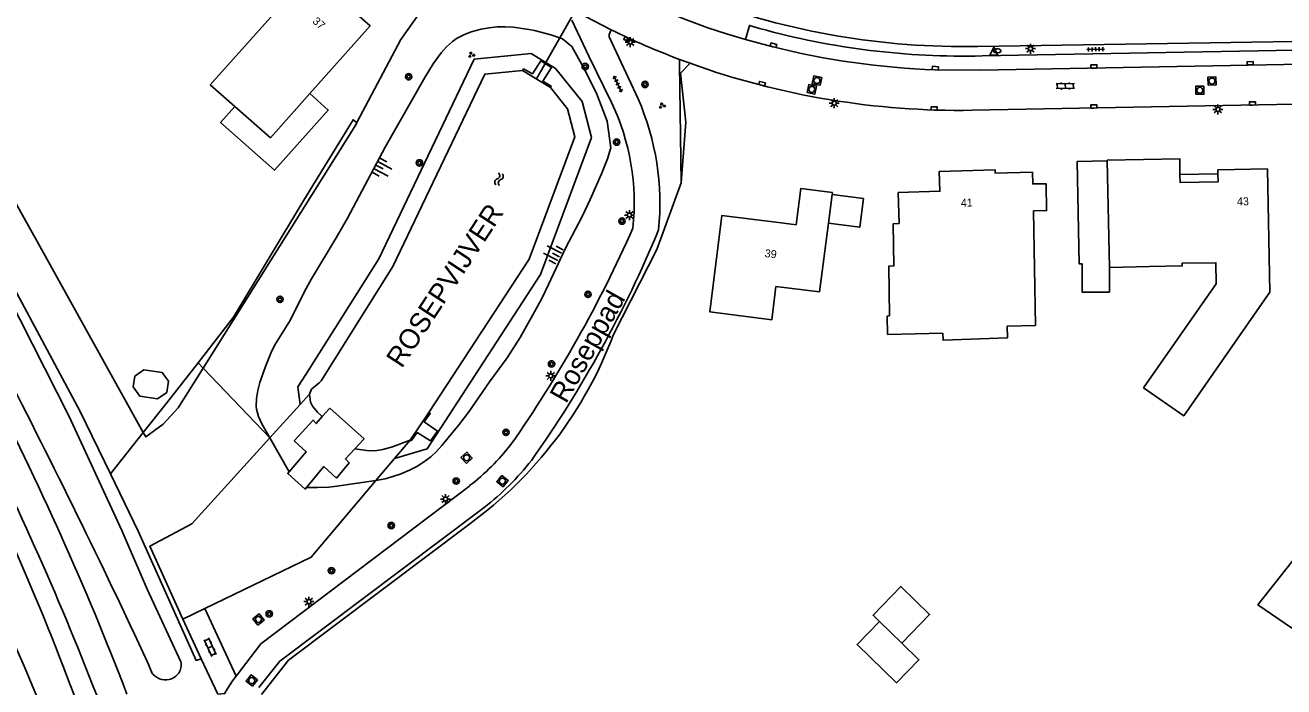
# Model space of a CAD drawing. Extents: x 126000 to 131009, y 393000 to 395500.
# Drawn here: x 130394.9 to 130552.1, y 394768.1 to 394850.8 of the extents above; entities that cross this region are included whole.
import ezdxf

# ---------------------------------------------------------------- set-up
doc = ezdxf.new("R2010")
doc.units = 0
for name, color, linetype in [('gg-afsc-erfafscheiding', 7, 'Continuous'), ('gg-afsc-hekwerk', 7, 'Continuous'), ('gg-anno-huisnummerreeks BGT', 7, 'Continuous'), ('gg-anno-naam water', 7, 'Continuous'), ('gg-anno-openbare ruimte label', 7, 'Continuous'), ('gg-bbg-gedigitaliseerde bebouwing', 7, 'Continuous'), ('gg-bbg-gedigitaliseerde bijgebouw', 7, 'Continuous'), ('gg-bbg-hoofdgebouw', 7, 'Continuous'), ('gg-bbg-luifel en loopbrug', 7, 'Continuous'), ('gg-knt-bovenkant onderkant talud', 7, 'Continuous'), ('gg-knt-verharding', 7, 'Continuous'), ('gg-knt-verharding nz', 7, 'Continuous'), ('gg-kntw-beschoeiing', 7, 'Continuous'), ('gg-kntw-bovenkant insteek waterloop', 7, 'Continuous'), ('gg-kwrk-duiker nz buis', 7, 'Continuous'), ('gg-kwrk-gemaal', 7, 'Continuous'), ('gg-kwrk-uitstroombak niveau min 01', 7, 'Continuous'), ('gt-grn-groengrens', 7, 'Continuous'), ('gt-symb-boom', 7, 'Continuous'), ('gt-symb-brandkraan', 7, 'Continuous'), ('gt-symb-groenvak', 7, 'Continuous'), ('gt-symb-klinker verharding', 7, 'Continuous'), ('gt-symb-kolk', 7, 'Continuous'), ('gt-symb-lichtmast', 7, 'Continuous'), ('gt-symb-rioolschacht', 7, 'Continuous'), ('gt-symb-talud symbool', 7, 'Continuous'), ('gt-symb-tegel verharding', 7, 'Continuous'), ('gt-symb-waterafsluiter', 7, 'Continuous'), ('gt-symb-watersymbool', 7, 'Continuous')]:
    doc.layers.add(name, color=color, linetype=linetype)

# ---------------------------------------------------------------- blocks, each defined once
blk = doc.blocks.new('gt0-RS')
at = {"layer": 'gt-symb-rioolschacht'}
blk.add_lwpolyline([(-0.5, -0.5), (0.5, -0.5), (0.5, 0.5), (-0.5, 0.5)], close=True, dxfattribs=at)
blk.add_circle((0, 0), 0.375, dxfattribs=at)
blk = doc.blocks.new('gt0-KOLK')
at = {"layer": 'gt-symb-kolk'}
blk.add_lwpolyline([(0, 0), (0.38, 0), (0.38, 0.4), (-0.37, 0.4), (-0.37, 0), (0, 0)], dxfattribs=at)
blk = doc.blocks.new('gt0-WAFSL')
at = {"layer": 'gt-symb-waterafsluiter'}
for p, q in [((-0.5, -0.33), (0, 0.67)), ((0, 0.67), (0.5, -0.33)), ((0.5, -0.33), (-0.5, -0.33))]:
    blk.add_line(p, q, dxfattribs=at)
blk = doc.blocks.new('gt0-BR')
at = {"layer": 'gt-symb-brandkraan'}
for centre, radius, start, end in [((-0.24, 0), 0.206, 107.5669, 252.4331), ((0.6, -2.66), 3, 106.892, 107.5669), ((0, -0.69), 0.938, 73.108, 106.892), ((-0.6, -2.66), 3, 72.4331, 73.108), ((0.24, 0), 0.206, 287.567, 72.4331), ((0.6, 2.66), 3, 252.4331, 253.108), ((0, 0.69), 0.938, 253.108, 286.8921), ((-0.6, 2.66), 3, 286.8921, 287.567)]:
    blk.add_arc(centre, radius, start, end, dxfattribs=at)
blk = doc.blocks.new('gt0-LMAST')
at = {"layer": 'gt-symb-lichtmast'}
for p, q in [((-0.18, 0.17), (-0.45, 0.44)), ((0, 0.25), (0, 0.62)), ((0.17, 0.17), (0.44, 0.44)), ((-0.25, 0), (-0.63, 0)), ((-0.18, -0.18), (-0.45, -0.45)), ((0, -0.25), (0, -0.63)), ((0.44, -0.45), (0.17, -0.18)), ((0.25, 0), (0.62, 0))]:
    blk.add_line(p, q, dxfattribs=at)
blk.add_circle((0, 0), 0.25, dxfattribs=at)
blk = doc.blocks.new('gt0-KL1')
at = {"layer": 'gt-symb-klinker verharding'}
for p, q in [((-1.15, 0.3), (1.15, 0.3)), ((-1, -0.3), (-1, 0.3)), ((-0.5, 0.3), (-0.5, 0.45)), ((0, -0.3), (0, 0.3)), ((0.5, 0.3), (0.5, 0.45)), ((1, -0.3), (1, 0.3)), ((-1.15, -0.3), (1.15, -0.3)), ((-0.5, -0.45), (-0.5, -0.3)), ((0.5, -0.45), (0.5, -0.3))]:
    blk.add_line(p, q, dxfattribs=at)
blk = doc.blocks.new('gt0-TEG1')
at = {"layer": 'gt-symb-tegel verharding'}
for p, q in [((-1.12, 0), (1.12, 0)), ((-0.9, -0.25), (-0.9, 0.25)), ((-0.45, -0.25), (-0.45, 0.25)), ((0, -0.25), (0, 0.25)), ((0.45, -0.25), (0.45, 0.25)), ((0.9, -0.25), (0.9, 0.25))]:
    blk.add_line(p, q, dxfattribs=at)
blk = doc.blocks.new('gt0-GRVAK')
at = {"layer": 'gt-symb-groenvak'}
for p, q in [((-0.11, 0.19), (-0.23, 0.24)), ((-0.18, 0.15), (0.09, 0.15)), ((-0.09, 0.21), (-0.16, 0.32)), ((-0.05, 0.21), (-0.05, 0.39)), ((0, 0.21), (0.06, 0.32)), ((0.01, 0.19), (0.13, 0.24)), ((0.26, -0.05), (0.2, 0.06)), ((0.3, -0.05), (0.3, 0.13)), ((0.35, -0.05), (0.41, 0.06)), ((-0.25, -0.23), (-0.36, -0.18)), ((-0.32, -0.26), (-0.05, -0.26)), ((-0.23, -0.21), (-0.29, -0.1)), ((-0.18, -0.2), (-0.18, -0.02)), ((-0.14, -0.21), (-0.07, -0.1)), ((-0.12, -0.23), (0, -0.18)), ((0.24, -0.07), (0.12, -0.02)), ((0.17, -0.11), (0.44, -0.11)), ((0.37, -0.07), (0.49, -0.02))]:
    blk.add_line(p, q, dxfattribs=at)
blk = doc.blocks.new('gt0-BOOM')
at = {"layer": 'gt-symb-boom'}
for radius in [0.4, 0.2]:
    blk.add_circle((0, 0), radius, dxfattribs=at)
blk = doc.blocks.new('gt0-TALUD_1')
at = {"layer": 'gt-symb-talud symbool'}
for p, q in [((-1, -1), (-1, 0)), ((-0.5, -2), (-0.5, 0)), ((0, -1), (0, 0)), ((0.5, -2), (0.5, 0)), ((1, -1), (1, 0))]:
    blk.add_line(p, q, dxfattribs=at)
blk = doc.blocks.new('gt0-WA')
at = {"layer": 'gt-symb-watersymbool'}
for centre, start, end in [((-0.32, 0.02), 28.0725, 151.9275), ((0.43, 0.42), 208.0725, 331.9275), ((-0.32, -0.43), 28.0725, 151.9275), ((0.43, -0.03), 208.0725, 331.9275)]:
    blk.add_arc(centre, 0.425, start, end, dxfattribs=at)

msp = doc.modelspace()

# ---------------------------------------------------------------- linework, layer by layer
at = {"layer": 'gg-afsc-erfafscheiding'}
for p, q in [((130476.62, 394845.94), (130476.81, 394831.13)), ((130476.81, 394831.13), (130473.77, 394822.79))]:
    msp.add_line(p, q, dxfattribs=at)
at = {"layer": 'gg-afsc-hekwerk'}
for p, q in [((130436.3, 394838.67), (130441.81, 394849.05)), ((130473.77, 394822.79), (130468.38, 394812.17)), ((130429.2, 394803.42), (130430.38, 394804.72)), ((130425.43, 394799.26), (130429.2, 394803.42)), ((130442.96, 394798.98), (130441.02, 394796.68)), ((130441.02, 394796.68), (130438.68, 394793.9)), ((130417.29, 394777.92), (130414.54, 394776.6))]:
    msp.add_line(p, q, dxfattribs=at)
for points in [[(130381.11, 394841.01), (130385.07, 394843.99), (130396.51, 394823.51), (130409.61, 394799.92)], [(130417.1, 394807.96), (130436.16, 394838.39), (130436.3, 394838.67)], [(130409.61, 394799.92), (130409.92, 394799.36), (130412.12, 394800.98), (130413.99, 394803), (130417.1, 394807.96)], [(130414.54, 394776.6), (130410.44, 394785.72), (130415.68, 394788.51), (130425.43, 394799.26)], [(130438.68, 394793.9), (130430.6, 394784.32), (130417.29, 394777.92)], [(130424.38, 394767.15), (130427.75, 394771.45), (130450.41, 394788.5)]]:
    msp.add_lwpolyline(points, dxfattribs=at)
msp.add_arc((130419.91, 394830.31), 51.75, 306.1088, 339.4837, dxfattribs=at)
at = {"layer": 'gg-bbg-gedigitaliseerde bebouwing'}
for p, q in [((130421.06, 394840.69), (130425.51, 394836.77)), ((130530.07, 394833.89), (130530.06, 394833.97)), ((130530.34, 394820.56), (130530.07, 394833.89)), ((130495.69, 394829.66), (130495.23, 394826.09)), ((130495.73, 394829.93), (130495.69, 394829.66)), ((130503.95, 394829.94), (130504.06, 394826.03)), ((130521.12, 394813.29), (130520.84, 394827.63)), ((130535.34, 394820.66), (130530.34, 394820.56))]:
    msp.add_line(p, q, dxfattribs=at)
for points in [[(130433.8, 394861.11), (130417.99, 394843.39), (130421.06, 394840.69)], [(130520.84, 394827.63), (130522.48, 394827.66), (130522.43, 394831.02), (130520.77, 394830.99), (130520.74, 394832.45)], [(130495.23, 394826.09), (130494.13, 394817.51), (130488.67, 394818.19)], [(130502.88, 394814.49), (130502.78, 394820.73), (130503.42, 394820.74), (130503.32, 394826.02), (130504.06, 394826.03)], [(130534.62, 394805.49), (130543.69, 394818.52), (130543.64, 394821.15), (130539.43, 394821.07), (130539.44, 394820.75), (130535.34, 394820.66)], [(130550.4, 394817.48), (130539.63, 394802), (130534.62, 394805.49)], [(130502.88, 394814.49), (130502.58, 394814.48), (130502.62, 394812.18), (130509.54, 394812.32)], [(130521.12, 394813.29), (130517.58, 394813.21), (130517.61, 394811.76), (130509.56, 394811.46), (130509.54, 394812.32)]]:
    msp.add_lwpolyline(points, dxfattribs=at)
at = {"layer": 'gg-bbg-gedigitaliseerde bijgebouw'}
msp.add_line((130501.61, 394776.3), (130504.39, 394773.6), dxfattribs=at)
for points in [[(130408.37, 394805.62), (130408.57, 394806.96), (130409.7, 394807.76), (130411.96, 394807.41), (130412.76, 394806.33), (130412.55, 394804.93), (130411.38, 394804.14), (130409.18, 394804.48), (130408.37, 394805.62)], [(130504.39, 394773.6), (130506.54, 394771.51), (130503.75, 394768.64), (130498.82, 394773.43), (130501.61, 394776.3)]]:
    msp.add_lwpolyline(points, dxfattribs=at)
at = {"layer": 'gg-bbg-hoofdgebouw'}
for p, q in [((130425.51, 394836.77), (130430.42, 394842.29)), ((130489.65, 394826.09), (130491.2, 394825.9))]:
    msp.add_line(p, q, dxfattribs=at)
for points in [[(130430.42, 394842.29), (130437.96, 394850.78), (130433.89, 394854.39), (130437.2, 394858.14), (130433.8, 394861.11)], [(130520.74, 394832.45), (130516.07, 394832.33), (130516.06, 394832.77), (130509.08, 394832.57), (130509.16, 394830.08), (130503.95, 394829.94)], [(130530.06, 394833.97), (130539.13, 394834.15), (130539.16, 394832.16)], [(130543.9, 394832.24), (130543.89, 394832.75), (130550.09, 394832.88), (130550.4, 394817.48)], [(130539.16, 394832.16), (130539.18, 394831.17), (130543.91, 394831.26), (130543.9, 394832.24)], [(130495.73, 394829.93), (130491.79, 394830.44), (130491.2, 394825.9)], [(130489.65, 394826.09), (130481.92, 394827.06), (130480.41, 394814.99), (130488.14, 394814.01), (130488.67, 394818.19)]]:
    msp.add_lwpolyline(points, dxfattribs=at)
at = {"layer": 'gg-bbg-luifel en loopbrug'}
msp.add_line((130539.16, 394832.16), (130543.9, 394832.24), dxfattribs=at)
for points in [[(130430.42, 394842.29), (130432.73, 394840.24), (130426.02, 394832.7), (130419.28, 394838.69), (130421.06, 394840.69)], [(130530.34, 394820.56), (130530.34, 394817.48), (130526.93, 394817.48), (130526.93, 394820.99), (130526.58, 394820.99), (130526.32, 394833.81), (130530.07, 394833.89)], [(130495.69, 394829.66), (130499.6, 394829.16), (130499.14, 394825.59), (130495.23, 394826.09)], [(130548.88, 394778.36), (130554.57, 394785.52), (130558.31, 394782.87), (130553.23, 394775.4), (130548.88, 394778.36)], [(130504.39, 394773.6), (130507.87, 394777.18), (130504.29, 394780.67), (130500.8, 394777.08), (130501.61, 394776.3)]]:
    msp.add_lwpolyline(points, dxfattribs=at)
at = {"layer": 'gg-knt-bovenkant onderkant talud'}
msp.add_line((130425.43, 394799.26), (130427.85, 394795), dxfattribs=at)
for points in [[(130438.68, 394793.9), (130439.82, 394794.14), (130440.78, 394794.41), (130441.72, 394794.73), (130442.88, 394795.22), (130443.78, 394795.68), (130444.64, 394796.19), (130445.53, 394796.86), (130446.25, 394797.55), (130446.91, 394798.3), (130449.07, 394800.92), (130450.31, 394802.5), (130452.87, 394806.25), (130455.08, 394809.27), (130456.7, 394811.8), (130458.5, 394814.99), (130459.44, 394816.76), (130460.26, 394818.42), (130462.37, 394822.95), (130464.47, 394826.93), (130465.47, 394829.05), (130466.86, 394832.26), (130467.61, 394834.13), (130468.02, 394835.5), (130467.57, 394838.84), (130466.28, 394842.24), (130464.84, 394845.17), (130463.18, 394848.2), (130462.01, 394849.12), (130460.56, 394849.62), (130458.51, 394850.17), (130457.53, 394850.36), (130455.83, 394850.58), (130454.83, 394850.63), (130453.82, 394850.62), (130452.82, 394850.53), (130451.83, 394850.36), (130450.59, 394850.02), (130449.65, 394849.64), (130448.77, 394849.17), (130448.25, 394848.8), (130447.5, 394848.15), (130446.82, 394847.4), (130445.83, 394846.03), (130444.78, 394844.32), (130439.85, 394835.58), (130435.12, 394826.71), (130433.72, 394824.27), (130430.62, 394819.12), (130429.78, 394817.56), (130427.99, 394813.99), (130426.15, 394811.02), (130425.64, 394810.03), (130424.89, 394808.19), (130424.19, 394806.15), (130423.92, 394805.15), (130423.75, 394804.16), (130423.73, 394803.18), (130423.77, 394802.85), (130424.02, 394801.91), (130424.43, 394801), (130425.43, 394799.26)], [(130430.02, 394793.04), (130431.38, 394793.04), (130432.79, 394793.09), (130433.78, 394793.19), (130438.68, 394793.9)]]:
    msp.add_lwpolyline(points, dxfattribs=at)
at = {"layer": 'gg-knt-verharding'}
for p, q in [((130463.76, 394852.53), (130468.09, 394850.25)), ((130477.94, 394846.08), (130476.62, 394846.57)), ((130597.7, 394841.79), (130513.19, 394840.2)), ((130421.24, 394769.46), (130417.29, 394777.92)), ((130416.85, 394771.64), (130414.54, 394776.6)), ((130418.91, 394767.22), (130416.85, 394771.64)), ((130403.27, 394768.39), (130405.32, 394763.47))]:
    msp.add_line(p, q, dxfattribs=at)
for points in [[(130468.13, 394841.18), (130465.28, 394846.98), (130463.17, 394851.49)], [(130471.44, 394841.64), (130467.83, 394849.4), (130467.82, 394849.66), (130468.09, 394850.25)], [(130480.16, 394850.51), (130482.5, 394849.75), (130484.87, 394849.06)], [(130486.63, 394850.43), (130485.36, 394850.82), (130484.87, 394849.06)], [(130590.38, 394849.18), (130556.04, 394848.51), (130556.04, 394848.86), (130513.89, 394848.18)], [(130514.43, 394847.01), (130553.46, 394847.74), (130554.39, 394845.98)], [(130421.24, 394769.46), (130424.3, 394773.48), (130450.4, 394793.27)], [(130452.21, 394790.54), (130426.67, 394771.34), (130424.06, 394768.04)], [(130418.91, 394767.22), (130419.82, 394767.27), (130419.9, 394767.5), (130420.77, 394768.85), (130421.24, 394769.46)]]:
    msp.add_lwpolyline(points, dxfattribs=at)
for centre, radius, start, end in [((130513.7, 394943.23), 98.6, 240.1093, 250.1118), ((130512.3, 394943.29), 95.13, 249.574, 270.9592), ((130511.56, 394939.35), 99.14, 243.9899, 249.3602), ((130512.13, 394942.88), 95.9, 254.5794, 271.3746), ((130511.64, 394939.52), 99.33, 250.1699, 270.8938), ((130441.53, 394828.59), 29.43, 353.9049, 25.3235), ((130441.45, 394828.57), 32.72, 354.1983, 23.5468), ((130323.4, 394890.7), 161.19, 325.0725, 336.1279), ((130336.41, 394882.26), 148.94, 324.8114, 337.4955), ((130049.54, 394629.94), 383.45, 20.978, 27.4057), ((130052.12, 394631.42), 376.92, 21.3087, 27.3799), ((130433.46, 394815.37), 27.84, 307.4648, 322.4906), ((130431.04, 394817.69), 34.43, 307.9412, 321.8843)]:
    msp.add_arc(centre, radius, start, end, dxfattribs=at)
at = {"layer": 'gg-knt-verharding nz'}
msp.add_line((130484.87, 394849.06), (130488.3, 394848.15), dxfattribs=at)
msp.add_lwpolyline([(130508.55, 394845.27), (130514.22, 394845.21), (130554.39, 394845.98)], dxfattribs=at)
msp.add_arc((130511.87, 394941.23), 96.02, 255.7939, 268.0196, dxfattribs=at)
at = {"layer": 'gg-kntw-beschoeiing'}
for points in [[(130431.61, 394806.11), (130431.83, 394806.36), (130440.78, 394820.68), (130452.29, 394844.73), (130457.01, 394845.18)], [(130460.48, 394843.06), (130462.63, 394840.4), (130463.53, 394836.9), (130457.83, 394821.58), (130445.29, 394802.42)], [(130430.38, 394804.72), (130430.63, 394805.32), (130431.61, 394806.11)], [(130430.38, 394804.72), (130430.51, 394803.73), (130430.76, 394803.23), (130431.4, 394802.45), (130431.98, 394801.9)], [(130436.06, 394797.89), (130437.55, 394797.65), (130438.55, 394797.64), (130439.55, 394797.78), (130440.76, 394798.13), (130442.96, 394798.98)]]:
    msp.add_lwpolyline(points, dxfattribs=at)
at = {"layer": 'gg-kntw-bovenkant insteek waterloop'}
msp.add_line((130410.14, 394771.22), (130410.67, 394769.9), dxfattribs=at)
for points in [[(130414.31, 394771.26), (130410.08, 394780.34), (130406.92, 394787.68), (130400.34, 394801.91), (130394.22, 394814), (130389.33, 394823.58), (130385.5, 394830.66), (130381.27, 394838.14), (130375.45, 394847.24), (130368.73, 394858.02), (130362.18, 394867.72), (130346.79, 394891.05), (130338.65, 394903.66), (130320.47, 394930.69), (130305.36, 394952.89), (130303.67, 394955.23), (130301.53, 394954.42), (130301.07, 394954)], [(130427.63, 394665.15), (130426.05, 394670.47), (130423.14, 394683.22), (130419.53, 394697.87), (130416.49, 394708.15), (130413.34, 394719.45), (130410.33, 394729.27), (130407.67, 394737.45), (130404.96, 394745.02), (130401.89, 394752.73), (130398.65, 394761.31), (130394.73, 394770.7), (130390.87, 394779.42), (130387.39, 394787.13), (130383.11, 394796.26), (130379.7, 394802.73), (130376.5, 394809.2), (130373.41, 394815.06), (130368.8, 394822.84), (130362.49, 394833.17), (130352.17, 394849.44), (130339.18, 394868.34), (130312.69, 394908.34), (130298.27, 394929.68)]]:
    msp.add_lwpolyline(points, dxfattribs=at)
for centre, radius, start, end in [((129502.49, 394348.89), 1001.1, 24.95233, 27.29306), ((130074.16, 394644.95), 348.89, 20.2997, 27.0208), ((130412.37, 394771.07), 2.07, 214.4018, 283.4916), ((130412.49, 394770.87), 1.86, 281.2515, 11.922)]:
    msp.add_arc(centre, radius, start, end, dxfattribs=at)
at = {"layer": 'gg-kwrk-duiker nz buis'}
msp.add_line((130458.75, 394844.12), (130471.78, 394867.17), dxfattribs=at)
at = {"layer": 'gg-kwrk-gemaal'}
for points in [[(130436.06, 394797.89), (130437.21, 394799.14), (130432.93, 394802.96), (130431.98, 394801.9)], [(130427.85, 394795), (130429.98, 394797.51), (130428.47, 394798.87), (130430.84, 394801.48), (130431.2, 394801.03), (130431.98, 394801.9)], [(130430.02, 394793.04), (130432.18, 394795.65), (130433.74, 394794.23), (130435.36, 394796.11), (130434.88, 394796.62), (130436.06, 394797.89)], [(130427.85, 394795), (130427.67, 394794.79), (130429.85, 394792.84), (130430.02, 394793.04)]]:
    msp.add_lwpolyline(points, dxfattribs=at)
at = {"layer": 'gg-kwrk-uitstroombak niveau min 01'}
for p, q in [((130460.48, 394843.06), (130457.01, 394845.18)), ((130445.29, 394802.42), (130442.96, 394798.98))]:
    msp.add_line(p, q, dxfattribs=at)
for points in [[(130457.01, 394845.18), (130457.13, 394845.38), (130458.23, 394844.75), (130459.29, 394846.38), (130460.61, 394845.55), (130459.56, 394843.84), (130460.58, 394843.22), (130460.48, 394843.06)], [(130442.96, 394798.98), (130443.08, 394798.89), (130443.85, 394799.91), (130445.5, 394798.86), (130446.4, 394800.1), (130444.73, 394801.24), (130445.48, 394802.3), (130445.29, 394802.42)]]:
    msp.add_lwpolyline(points, dxfattribs=at)
at = {"layer": 'gt-grn-groengrens'}
for p, q in [((130449.98, 394860.83), (130441.81, 394849.05)), ((130476.62, 394845.94), (130476.62, 394846.57)), ((130416.47, 394808.61), (130417.1, 394807.96)), ((130417.1, 394807.96), (130425.43, 394799.26)), ((130409.61, 394799.92), (130405.52, 394794.77))]:
    msp.add_line(p, q, dxfattribs=at)
for points in [[(130441.02, 394796.68), (130445.09, 394797.88), (130459.26, 394819.68), (130465.62, 394836.79), (130464.46, 394841.32), (130461.14, 394845.42), (130458.09, 394847.29), (130450.98, 394846.61), (130439.03, 394821.64), (130429.92, 394807.18), (130428.92, 394805.61), (130429.2, 394803.42)], [(130476.81, 394831.13), (130477.41, 394838.73), (130476.76, 394844.86), (130477.94, 394846.08)], [(130405.52, 394794.77), (130401.74, 394802.56), (130381.11, 394841.01)], [(130436.3, 394838.67), (130435.84, 394839.02), (130429.68, 394828.97), (130420.87, 394814.34), (130416.47, 394808.61)], [(130416.47, 394808.61), (130412.55, 394803.63), (130409.61, 394799.92)], [(130416.85, 394771.64), (130416.21, 394771.43), (130409.01, 394787.51), (130405.52, 394794.77)]]:
    msp.add_lwpolyline(points, dxfattribs=at)

# ---------------------------------------------------------------- block references
at = {"layer": 'gt-symb-boom'}
for p in [(130464.84, 394845.68), (130442.78, 394844.4), (130472.31, 394843.44), (130468.76, 394836.23), (130444.12, 394833.63), (130469.44, 394826.35), (130426.7, 394816.57), (130465.18, 394817.19), (130460.63, 394808.49), (130454.94, 394799.94), (130448.72, 394793.85), (130440.6, 394788.28), (130433.13, 394782.65), (130425.35, 394777.24)]:
    msp.add_blockref('gt0-BOOM', p, dxfattribs=at)
at = {"layer": 'gt-symb-brandkraan'}
msp.add_blockref('gt0-BR', (130516.32, 394847.63), dxfattribs=at)
at = {"layer": 'gt-symb-groenvak'}
for p in [(130450.6, 394847.13), (130474.43, 394840.77)]:
    msp.add_blockref('gt0-GRVAK', p, dxfattribs=at)
at = {"layer": 'gt-symb-klinker verharding'}
for p, rotation in [((130524.83, 394843.24), 0.973934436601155), ((130417.97, 394773.08), -65.40899949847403)]:
    msp.add_blockref('gt0-KL1', p, dxfattribs=dict(at, rotation=rotation))
at = {"layer": 'gt-symb-kolk'}
for p, rotation in [((130470.16, 394849.27), 155.66512570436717), ((130488.3, 394848.15), -14.898187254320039), ((130508.55, 394845.27), -4.877880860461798), ((130528.4, 394845.48), 1.088488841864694), ((130547.92, 394845.88), 1.1457628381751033), ((130486.89, 394843.33), -14.119602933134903), ((130508.44, 394840.24), -1.4893547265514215), ((130528.39, 394840.49), 1.088488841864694), ((130548.22, 394840.86), 1.088488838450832)]:
    msp.add_blockref('gt0-KOLK', p, dxfattribs=dict(at, rotation=rotation))
at = {"layer": 'gt-symb-lichtmast'}
for p in [(130470.46, 394848.74), (130520.48, 394847.91), (130495.96, 394841.09), (130543.9, 394840.32), (130470.37, 394827.11), (130460.54, 394807), (130447.38, 394791.6), (130430.31, 394778.77)]:
    msp.add_blockref('gt0-LMAST', p, dxfattribs=at)
at = {"layer": 'gt-symb-rioolschacht'}
for p, rotation in [((130493.8, 394843.92), -11.590736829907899), ((130543.15, 394843.86), 1.088488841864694), ((130493.15, 394842.82), -11.590736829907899), ((130541.64, 394842.71), 1.088488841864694), ((130450.02, 394796.76), 42.04255015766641), ((130454.49, 394793.84), -128.17653760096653), ((130424.01, 394776.54), 37.1563741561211), ((130423.17, 394768.9), 51.53705293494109)]:
    msp.add_blockref('gt0-RS', p, dxfattribs=dict(at, rotation=rotation))
at = {"layer": 'gt-symb-talud symbool'}
for p, xscale, yscale, rotation in [((130438.69, 394833.34), 0.9998249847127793, 0.9998249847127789, 62.025270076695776), ((130461.64, 394821.88), 1.0000719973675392, 1.0000719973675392, -117.38497057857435)]:
    msp.add_blockref('gt0-TALUD_1', p, dxfattribs=dict(at, xscale=xscale, yscale=yscale, rotation=rotation))
at = {"layer": 'gt-symb-tegel verharding'}
for p, rotation in [((130528.62, 394847.83), 0.973934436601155), ((130468.91, 394843.49), -64.66472300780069)]:
    msp.add_blockref('gt0-TEG1', p, dxfattribs=dict(at, rotation=rotation))
at = {"layer": 'gt-symb-waterafsluiter'}
msp.add_blockref('gt0-WAFSL', (130515.89, 394847.42), dxfattribs=at)
at = {"layer": 'gt-symb-watersymbool', "rotation": 76.99249520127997}
msp.add_blockref('gt0-WA', (130454.05, 394831.53), dxfattribs=at)

# ---------------------------------------------------------------- texts
at = {"layer": 'gg-anno-huisnummerreeks BGT'}
for s, rotation, p in [('37', 318.5, (130430.68, 394851.22)), ('41', 1.7, (130511.79, 394828.14)), ('43', 1.1, (130546.29, 394828.3)), ('39', 352.9, (130487.22, 394821.86))]:
    msp.add_text(s, height=1, rotation=rotation, dxfattribs=at).set_placement(p)
at = {"layer": 'gg-anno-naam water'}
msp.add_text('ROSEPVIJVER', height=2.5, rotation=56.7865, dxfattribs=at).set_placement((130441.91, 394807.85))
at = {"layer": 'gg-anno-openbare ruimte label'}
msp.add_text('Roseppad', height=2.5, rotation=60.6, dxfattribs=at).set_placement((130462.45, 394803.44))

doc.saveas('drawing.dxf')
